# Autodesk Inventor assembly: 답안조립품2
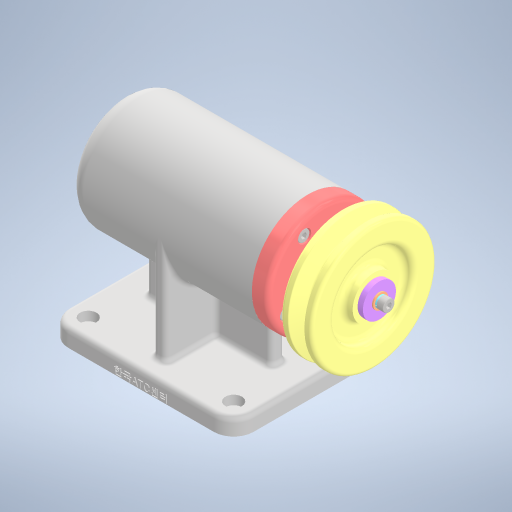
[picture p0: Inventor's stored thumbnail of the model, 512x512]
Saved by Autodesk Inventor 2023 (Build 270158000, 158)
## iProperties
Created: 2026-08
Part Number: 답안조립품2
Document SubType Name: Assembly
Designer: 4강의실
Author: 4강의실
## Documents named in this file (14)
- C:\Users\kimgi\Desktop\760803V1001\답안조립품2.iam
- C:\Users\kimgi\Desktop\760803V1001\부품.ipt
- C:\Users\kimgi\Desktop\760603V1008\6각 구멍붙이 볼트 M4x12.ipt
- C:\Users\kimgi\Desktop\760603V1008\V 벨트 풀리.ipt
- C:\Users\kimgi\Desktop\760603V1008\깊은 홈 볼 베어링 6004.ipt
- C:\Users\kimgi\Desktop\760603V1008\스러스트 볼 베어링 51202.ipt
- C:\Users\kimgi\Desktop\760603V1008\스프링 와셔 M4.ipt
- C:\Users\kimgi\Desktop\760603V1008\어댑터 슬리브.ipt
- C:\Users\kimgi\Desktop\760603V1008\엔드 캡.ipt
- C:\Users\kimgi\Desktop\760603V1008\오일 실 20 32 5.ipt
- C:\Users\kimgi\Desktop\760603V1008\축.ipt
- C:\Users\kimgi\Desktop\760603V1008\커버.ipt
- C:\Users\kimgi\Desktop\760603V1008\평 와셔 M4.ipt
- C:\Users\kimgi\Desktop\760603V1008\평행 키 5x5x16.ipt
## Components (7 placed, 2 different names)
1. V 벨트 풀리:1 — 각도:3
2. 6각 구멍붙이 볼트 M4x12:2
3. 6각 구멍붙이 볼트 M4x12:7
4. 6각 구멍붙이 볼트 M4x12:3
5. 6각 구멍붙이 볼트 M4x12:4
6. 6각 구멍붙이 볼트 M4x12:5
7. 6각 구멍붙이 볼트 M4x12:6
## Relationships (1: Angle 1)
- 각도:3 [Angle]: V 벨트 풀리:1
